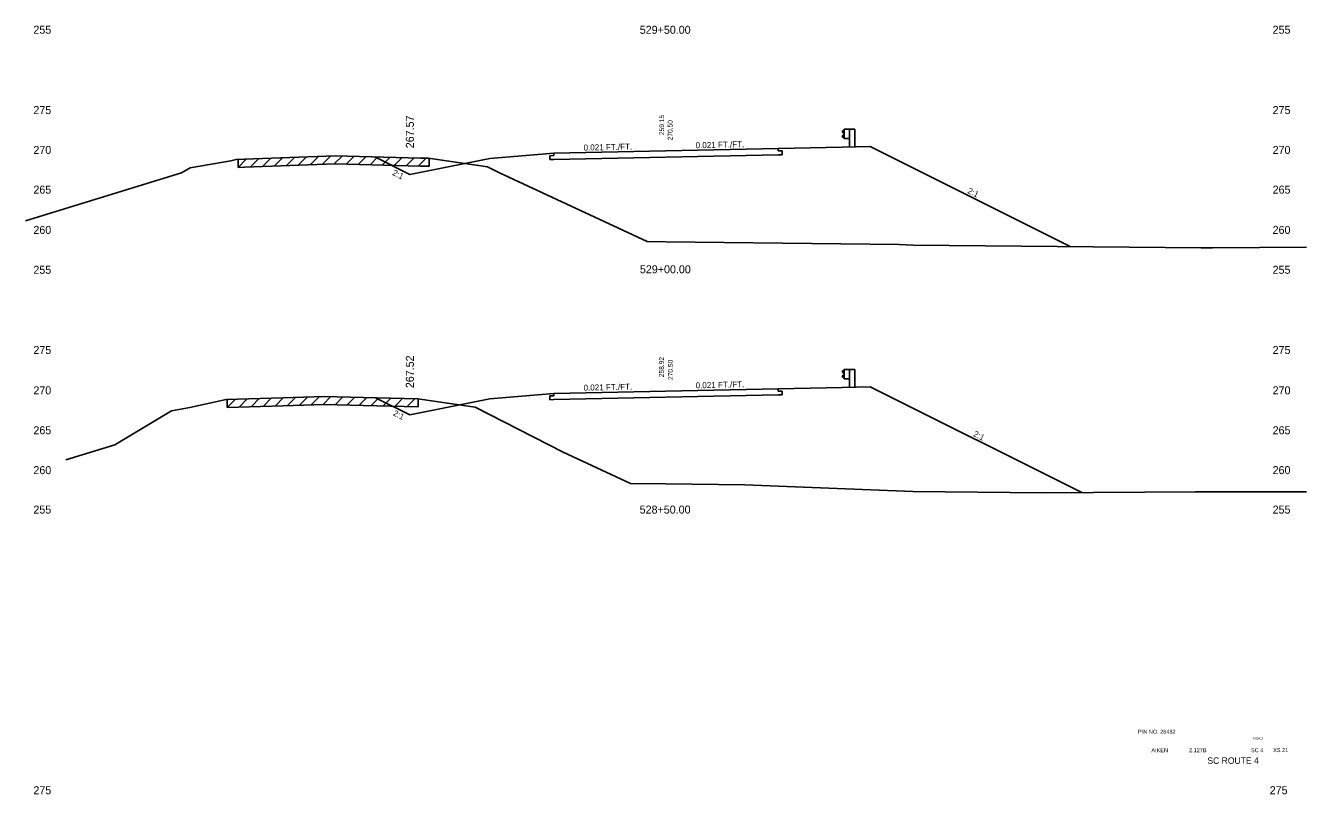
# Model space of a CAD drawing. Extents: x 883 to 1160, y 1002 to 4323.
# Drawn here: x 1000 to 1160, y 3395.1 to 3491.2 of the extents above; entities that cross this region are included whole.
import ezdxf

# ---------------------------------------------------------------- set-up
doc = ezdxf.new("R2010")
doc.units = 0
for name, color, linetype in [('Level 1', 7, 'Continuous'), ('Level 10', 7, 'Continuous'), ('Level 11', 7, 'Continuous'), ('Level 12', 7, 'Continuous'), ('Level 24', 7, 'Continuous'), ('Level 3', 7, 'Continuous'), ('Level 32', 7, 'Continuous'), ('Level 33', 7, 'Continuous'), ('Level 59', 7, 'Continuous'), ('Level 6', 7, 'Continuous'), ('Level 60', 7, 'Continuous'), ('Level 61', 7, 'Continuous'), ('Level 7', 7, 'Continuous')]:
    doc.layers.add(name, color=color, linetype=linetype)

msp = doc.modelspace()

# ---------------------------------------------------------------- linework, layer by layer
at = {"layer": 'Level 11'}
for p, q in [((1066, 3475.21), (1066, 3474.91)), ((1094, 3475.49), (1094, 3475.79)), ((1094.5, 3475.5), (1094, 3475.49)), ((1094.5, 3475.02), (1094.5, 3475.5)), ((1066, 3474.91), (1065.5, 3474.9)), ((1065.5, 3474.9), (1065.5, 3474.42)), ((1065.5, 3474.42), (1066, 3474.43)), ((1094, 3475.01), (1094.5, 3475.02)), ((1066, 3444.91), (1065.5, 3444.9)), ((1065.5, 3444.9), (1065.5, 3444.42)), ((1066, 3445.21), (1066, 3444.91)), ((1094, 3445.49), (1094, 3445.79)), ((1094.5, 3445.5), (1094, 3445.49)), ((1094, 3445.01), (1094.5, 3445.02)), ((1094.5, 3445.02), (1094.5, 3445.5)), ((1065.5, 3444.42), (1066, 3444.43))]:
    msp.add_line(p, q, dxfattribs=at)
at = {"layer": 'Level 12'}
for p, q in [((1080, 3474.72), (1066, 3474.43)), ((1094, 3475.01), (1080, 3474.72)), ((1094, 3445.01), (1080, 3444.72)), ((1080, 3444.72), (1066, 3444.43))]:
    msp.add_line(p, q, dxfattribs=at)
at = {"layer": 'Level 24'}
for p, q in [((1102.27, 3478.13), (1102, 3477.93)), ((1102, 3477.93), (1102, 3477.88)), ((1102, 3477.88), (1102.27, 3477.68)), ((1102, 3477.36), (1102.27, 3477.56)), ((1102, 3477.31), (1102, 3477.36)), ((1102.27, 3477.11), (1102, 3477.31)), ((1102.27, 3477.04), (1102.27, 3478.21)), ((1102.27, 3478.21), (1102.94, 3478.21)), ((1102.27, 3477.04), (1102.94, 3477.04)), ((1102.94, 3478.21), (1102.94, 3475.98)), ((1102.94, 3478.21), (1103.6, 3478.21)), ((1103.6, 3478.21), (1103.6, 3475.99)), ((1102.27, 3448.13), (1102, 3447.93)), ((1102.27, 3447.04), (1102.27, 3448.21)), ((1102.27, 3448.21), (1102.94, 3448.21)), ((1102.94, 3448.21), (1102.94, 3445.98)), ((1102.94, 3448.21), (1103.6, 3448.21)), ((1103.6, 3448.21), (1103.6, 3445.99)), ((1102, 3447.93), (1102, 3447.88)), ((1102, 3447.88), (1102.27, 3447.68)), ((1102, 3447.36), (1102.27, 3447.56)), ((1102, 3447.31), (1102, 3447.36)), ((1102.27, 3447.11), (1102, 3447.31)), ((1102.27, 3447.04), (1102.94, 3447.04))]:
    msp.add_line(p, q, dxfattribs=at)
at = {"layer": 'Level 59'}
for p, q in [((1066, 3475.21), (1080, 3475.5)), ((1080, 3475.5), (1094, 3475.79)), ((1066, 3445.21), (1080, 3445.5)), ((1080, 3445.5), (1094, 3445.79))]:
    msp.add_line(p, q, dxfattribs=at)
at = {"layer": 'Level 6'}
for p, q in [((1058, 3474.54), (1066, 3475.21)), ((1094, 3475.79), (1102, 3475.96)), ((1102, 3475.96), (1105.5, 3476.03)), ((1058, 3444.54), (1066, 3445.21)), ((1094, 3445.79), (1102, 3445.96)), ((1102, 3445.96), (1105.5, 3446.03))]:
    msp.add_line(p, q, dxfattribs=at)
at = {"layer": 'Level 60'}
for p, q in [((1020.56, 3473.4), (1025.63, 3474.28)), ((1025.63, 3474.28), (1026.3, 3474.42)), ((1026.3, 3474.42), (1027.35, 3474.45)), ((1027.35, 3474.45), (1038.67, 3474.87)), ((1038.67, 3474.87), (1049.34, 3474.61)), ((1049.34, 3474.61), (1050.29, 3474.58)), ((1050.29, 3474.58), (1050.86, 3474.5)), ((1050.86, 3474.5), (1057.71, 3473.51)), ((1000, 3466.75), (1019.46, 3472.74)), ((1019.46, 3472.74), (1020.56, 3473.4)), ((1057.71, 3473.51), (1059.19, 3472.76)), ((1059.19, 3472.76), (1077.65, 3464.18)), ((1077.65, 3464.18), (1080, 3464.15)), ((1080, 3464.15), (1109.11, 3463.81)), ((1109.11, 3463.81), (1110.87, 3463.74)), ((1110.87, 3463.74), (1146.86, 3463.38)), ((1146.86, 3463.38), (1147.74, 3463.39)), ((1147.74, 3463.39), (1148.26, 3463.39)), ((1148.26, 3463.39), (1160, 3463.46)), ((1032.14, 3444.64), (1037.31, 3444.83)), ((1037.31, 3444.83), (1042.18, 3444.71)), ((1018.22, 3443.04), (1020.51, 3443.44)), ((1020.51, 3443.44), (1025.07, 3444.43)), ((1025.07, 3444.43), (1032.14, 3444.64)), ((1042.18, 3444.71), (1048.98, 3444.54)), ((1048.98, 3444.54), (1053.01, 3443.96)), ((1053.01, 3443.96), (1056.15, 3443.5)), ((1056.15, 3443.5), (1067.15, 3437.88)), ((1011.14, 3438.8), (1018.22, 3443.04)), ((1005.03, 3436.92), (1011.14, 3438.8)), ((1067.15, 3437.88), (1075.57, 3433.97)), ((1075.57, 3433.97), (1080, 3433.92)), ((1080, 3433.92), (1089.85, 3433.8)), ((1089.85, 3433.8), (1110.85, 3432.95)), ((1110.85, 3432.95), (1127.05, 3432.79)), ((1127.05, 3432.79), (1146.13, 3432.9)), ((1146.13, 3432.9), (1157.43, 3432.9)), ((1157.43, 3432.9), (1160, 3432.91))]:
    msp.add_line(p, q, dxfattribs=at)
at = {"layer": 'Level 61'}
for p, q in [((1027.57, 3474.46), (1026.54, 3473.43)), ((1026.54, 3474.43), (1026.54, 3473.43)), ((1027.35, 3473.45), (1038.67, 3473.87)), ((1029.08, 3474.52), (1028.04, 3473.48)), ((1030.58, 3474.57), (1029.54, 3473.53)), ((1032.08, 3474.63), (1031.04, 3473.59)), ((1033.58, 3474.68), (1032.54, 3473.64)), ((1035.08, 3474.74), (1034.04, 3473.7)), ((1036.58, 3474.79), (1035.55, 3473.76)), ((1038.09, 3474.85), (1037.05, 3473.81)), ((1039.53, 3474.85), (1038.55, 3473.87)), ((1038.67, 3473.87), (1049.34, 3473.61)), ((1041.02, 3474.81), (1040.05, 3473.84)), ((1042.52, 3474.78), (1041.55, 3473.8)), ((1044.02, 3474.74), (1043.05, 3473.76)), ((1045.53, 3474.7), (1044.55, 3473.73)), ((1047.03, 3474.66), (1046.05, 3473.69)), ((1048.53, 3474.63), (1047.55, 3473.65)), ((1050.03, 3474.59), (1049.05, 3473.61)), ((1049.34, 3473.61), (1050.29, 3473.58)), ((1050.4, 3473.57), (1050.4, 3474.57)), ((1026.54, 3473.43), (1027.35, 3473.45)), ((1050.29, 3473.58), (1050.4, 3473.57)), ((1036.7, 3444.81), (1035.66, 3443.77)), ((1038.15, 3444.81), (1037.17, 3443.82)), ((1026.19, 3444.46), (1025.16, 3443.43)), ((1025.16, 3444.43), (1025.16, 3443.43)), ((1025.16, 3443.43), (1032.14, 3443.64)), ((1027.69, 3444.51), (1026.66, 3443.48)), ((1029.19, 3444.55), (1028.16, 3443.52)), ((1030.69, 3444.59), (1029.66, 3443.56)), ((1032.19, 3444.64), (1031.16, 3443.61)), ((1032.14, 3443.64), (1037.31, 3443.83)), ((1033.7, 3444.69), (1032.66, 3443.66)), ((1035.2, 3444.75), (1034.16, 3443.71)), ((1037.31, 3443.83), (1042.18, 3443.71)), ((1039.64, 3444.77), (1038.67, 3443.79)), ((1041.14, 3444.73), (1040.17, 3443.76)), ((1042.64, 3444.7), (1041.67, 3443.72)), ((1042.18, 3443.71), (1048.98, 3443.54)), ((1044.14, 3444.66), (1043.17, 3443.68)), ((1045.64, 3444.62), (1044.67, 3443.65)), ((1047.14, 3444.59), (1046.17, 3443.61)), ((1048.65, 3444.55), (1047.67, 3443.58)), ((1048.98, 3443.54), (1049.02, 3443.54)), ((1049.02, 3443.54), (1049.02, 3444.54))]:
    msp.add_line(p, q, dxfattribs=at)
at = {"layer": 'Level 7'}
for p, q in [((1105.5, 3476.03), (1130.47, 3463.54)), ((1043.63, 3474.75), (1048, 3472.57)), ((1048, 3472.57), (1058, 3474.54)), ((1105.5, 3446.03), (1131.93, 3432.82)), ((1043.69, 3444.67), (1048, 3442.52)), ((1048, 3442.52), (1058, 3444.54))]:
    msp.add_line(p, q, dxfattribs=at)

# ---------------------------------------------------------------- texts
at = {"layer": 'Level 1'}
for s, height, p in [('529+50.00', 1, (1076.72, 3490.13)), ('529+00.00', 1, (1076.74, 3460.21)), ('528+50.00', 1, (1076.71, 3430.19)), ('PIN NO. 26432', 0.5, (1138.97, 3402.69)), ('AIKEN', 0.5, (1140.64, 3400.38)), (' 2.127B', 0.5, (1145.15, 3400.38)), ('SC 4', 0.5, (1153.09, 3400.38)), ('XS 21', 0.5, (1155.85, 3400.39)), ('SC ROUTE 4', 0.8, (1147.63, 3398.93))]:
    msp.add_text(s, height=height, dxfattribs=at).set_placement(p)
at = {"layer": 'Level 10'}
for s, p in [('259.15', (1079.76, 3477.47)), ('258.92', (1079.73, 3447.23))]:
    msp.add_text(s, height=0.6, rotation=90, dxfattribs=at).set_placement(p)
at = {"layer": 'Level 3'}
for s, height, p in [(' 255', 1, (1000.6, 3490.14)), (' 255', 1, (1155.41, 3490.14)), (' 275', 1, (1000.6, 3480.1)), (' 275', 1, (1155.41, 3480.1)), (' 270', 1, (1000.6, 3475.12)), (' 270', 1, (1155.41, 3475.12)), (' 265', 1, (1000.6, 3470.16)), (' 265', 1, (1155.41, 3470.16)), (' 260', 1, (1000.6, 3465.13)), (' 260', 1, (1155.41, 3465.13)), (' 255', 1, (1000.6, 3460.15)), (' 255', 1, (1155.41, 3460.15)), (' 275', 1, (1000.6, 3450.13)), (' 275', 1, (1155.41, 3450.13)), (' 270', 1, (1000.6, 3445.09)), (' 270', 1, (1155.41, 3445.09)), (' 265', 1, (1000.6, 3440.1)), (' 265', 1, (1155.41, 3440.1)), (' 260', 1, (1000.6, 3435.12)), (' 260', 1, (1155.41, 3435.12)), (' 255', 1, (1000.6, 3430.19)), (' 255', 1, (1155.41, 3430.19)), ('ROAD', 0.3, (1153.38, 3401.96)), (' 275', 1, (1000.6, 3395.13)), (' 275', 1, (1155.05, 3395.13))]:
    msp.add_text(s, height=height, dxfattribs=at).set_placement(p)
at = {"layer": 'Level 32'}
for s, rotation, p in [('0.021 FT./FT.', 1.1916, (1069.71, 3475.54)), ('0.021 FT./FT.', 1.1916, (1083.71, 3475.83)), ('2:1', 333.435, (1045.75, 3472.53)), ('2:1', 333.435, (1117.59, 3470.26)), ('0.021 FT./FT.', 1.1916, (1069.71, 3445.54)), ('0.021 FT./FT.', 1.1916, (1083.71, 3445.83)), ('2:1', 333.435, (1045.83, 3442.49)), ('2:1', 333.435, (1118.32, 3439.9))]:
    msp.add_text(s, height=0.75, rotation=rotation, dxfattribs=at).set_placement(p)
at = {"layer": 'Level 33'}
for s, p in [('267.57', (1048.5, 3475.83)), ('267.52', (1048.5, 3445.86))]:
    msp.add_text(s, height=1, rotation=90, dxfattribs=at).set_placement(p)
at = {"layer": 'Level 59'}
for p in [(1080.82, 3476.59), (1080.85, 3446.65)]:
    msp.add_text(' 270.50', height=0.6, rotation=90, dxfattribs=at).set_placement(p)

doc.saveas('drawing.dxf')
